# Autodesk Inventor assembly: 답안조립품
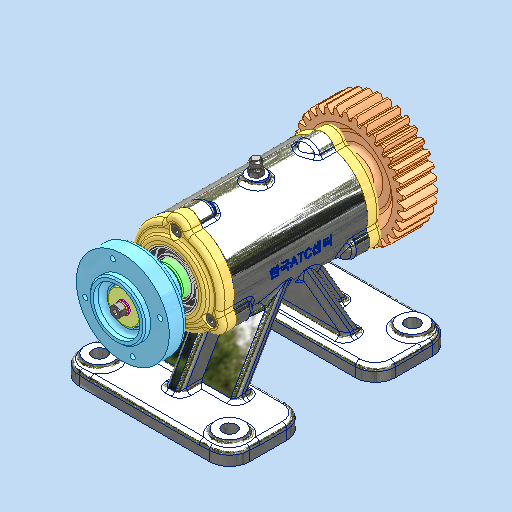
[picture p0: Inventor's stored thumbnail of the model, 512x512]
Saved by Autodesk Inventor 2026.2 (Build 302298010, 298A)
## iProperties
Created: 2026-04
Part Number: 답안조립품
Document SubType Name: Assembly
Designer: PC-2-06
Author: PC-2-06
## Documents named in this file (16)
- C:\Users\PC-2-06\Desktop\760403V1017\답안조립품.iam
- C:\Users\PC-2-06\Desktop\760403V1017\본체.ipt
- C:\Users\PC-2-06\Desktop\760403V1017\6각 구멍붙이 볼트 M4x12\6각 구멍붙이 볼트 M4x12.ipt
- C:\Users\PC-2-06\Desktop\760403V1017\그리스 니플 M6x0,75\그리스 니플 M6x0,75.ipt
- C:\Users\PC-2-06\Desktop\760403V1017\깊은 홈 볼 베어링 6004\깊은 홈 볼 베어링 6004.ipt
- C:\Users\PC-2-06\Desktop\760403V1017\스퍼 기어\스퍼 기어.ipt
- C:\Users\PC-2-06\Desktop\760403V1017\스프링 와셔 M4\스프링 와셔 M4.ipt
- C:\Users\PC-2-06\Desktop\760403V1017\실링\실링.ipt
- C:\Users\PC-2-06\Desktop\760403V1017\엔드 캡\엔드 캡.ipt
- C:\Users\PC-2-06\Desktop\760403V1017\오일 실 20 35 8\오일 실 20 35 8.ipt
- C:\Users\PC-2-06\Desktop\760403V1017\축\축.ipt
- C:\Users\PC-2-06\Desktop\760403V1017\커버\커버.ipt
- C:\Users\PC-2-06\Desktop\760403V1017\평 와셔 M4\평 와셔 M4.ipt
- C:\Users\PC-2-06\Desktop\760403V1017\평행 키 4x4x14\평행 키 4x4x14.ipt
- C:\Users\PC-2-06\Desktop\760403V1017\플랜지\플랜지.ipt
- C:\Users\PC-2-06\Desktop\760403V1017\플러그 M6x0,75\플러그 M6x0,75.ipt
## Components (11 placed, 4 different names)
1. 6각 구멍붙이 볼트 M4x12:1
2. 그리스 니플 M6x0,75:1
3. 플랜지:1
4. 플러그 M6x0,75:1
5. 6각 구멍붙이 볼트 M4x12:2
6. 6각 구멍붙이 볼트 M4x12:3
7. 6각 구멍붙이 볼트 M4x12:4
8. 6각 구멍붙이 볼트 M4x12:5
9. 6각 구멍붙이 볼트 M4x12:7
10. 6각 구멍붙이 볼트 M4x12:8
11. 6각 구멍붙이 볼트 M4x12:9
